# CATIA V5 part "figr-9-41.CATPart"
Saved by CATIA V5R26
Part number: Part1
Bounding box of the stored display mesh (mm): x -40 to 40, y -20.616 to 191.034, z 0 to 131.022
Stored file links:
  D:\_Deepak\CATIA\CATIA V5-6R2016_Deepak\Resources\Part files\Partfiles\c09_catia_v5_6r2016_prt\figr-9-41.CATPart
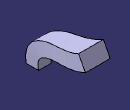
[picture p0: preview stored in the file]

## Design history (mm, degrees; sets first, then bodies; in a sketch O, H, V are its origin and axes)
Set1
  Plane1: type Normal, Curve Sketch2, RefPoint vertex of Sketch2
Body1 (main body)
  Sketch1 on xy-plane, origin (0, 0, 0), H (1, 0, 0), V (0, 1, 0)
    line L1 (20, 20) -> (20, -20)
    line L2 (20, -20) -> (-20, -20)
    line L3 (-20, -20) -> (-20, 20)
    line L4 (-20, 20) -> (20, 20)
    vertical: L1 V, L3 V
    horizontal: L2 H, L4 H
    equidistance: L1 L3 O, L2 L4 O
  Sketch2 on yz-plane, origin (0, 0, 0), H (0, 1, 0), V (0, 0, 1)
    spline S1 through (0, 0) (20, 60) (60, 80) (120, 90) (180, 110)
    point P1 (0, 0)
    coincidence: P1 O
  Sketch3 on Plane1, origin (0, 186.3865, 97.8327), H (1, 0, 0), V (0, -0.4648, 0.8854)
    point P1 (0, 13.7415)
    line L1 (40, 37.4831) -> (40, -10)
    line L2 (40, -10) -> (-40, -10)
    line L3 (-40, -10) -> (-40, 37.4831)
    line L4 (-40, 37.4831) -> (40, 37.4831)
    reference projected point E1 (0, 13.7415) from vertex of Sketch2
    coincidence: P1 V, P1 E1
    vertical: L1 V, L3 V
    horizontal: L2 H, L4 H
    equidistance: L1 L3 P1, L2 L4 P1
  Loft1: Sections (Sketch1; Sketch3), Spine Sketch2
